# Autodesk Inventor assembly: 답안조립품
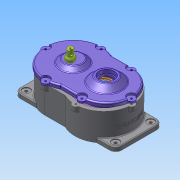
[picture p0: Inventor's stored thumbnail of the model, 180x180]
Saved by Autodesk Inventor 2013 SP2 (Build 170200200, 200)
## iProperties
Created: 2025-09
Part Number: 답안조립품
Document SubType Name: Assembly
Designer: a
Author: a
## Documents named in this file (18)
- C:\Users\a\Desktop\750903V1015\답안조립품.iam
- C:\Users\a\Desktop\750903V1015\본체.ipt
- C:\Users\a\Desktop\750903V1015\구동 축.ipt
- C:\Users\a\Desktop\750903V1015\오일 실 20 35 8.ipt
- C:\Users\a\Desktop\750903V1015\깊은 홈 볼 베어링 6904.ipt
- C:\Users\a\Desktop\750903V1015\평행 키 6x6x14.ipt
- C:\Users\a\Desktop\750903V1015\구동 휠.ipt
- C:\Users\a\Desktop\750903V1015\칼라.ipt
- C:\Users\a\Desktop\750903V1015\커버.ipt
- C:\Users\a\Desktop\750903V1015\스러스트 볼 베어링 51102.ipt
- C:\Users\a\Desktop\750903V1015\슬롯 축.ipt
- C:\Users\a\Desktop\750903V1015\6각 구멍붙이 볼트 M6x12.ipt
- C:\Users\a\Desktop\750903V1015\어댑터.ipt
- C:\Users\a\Desktop\750903V1015\슬롯.ipt
- C:\Users\a\Desktop\750903V1015\캠 플로워.ipt
- C:\Users\a\Desktop\750903V1015\평 와셔 M3.ipt
- C:\Users\a\Desktop\750903V1015\스프링 와셔 M3.ipt
- C:\Users\a\Desktop\750903V1015\육각 너트 M3.ipt
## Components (3 placed, 3 different names)
1. 구동 축:1
2. 구동 휠:1
3. 6각 구멍붙이 볼트 M6x12:1
